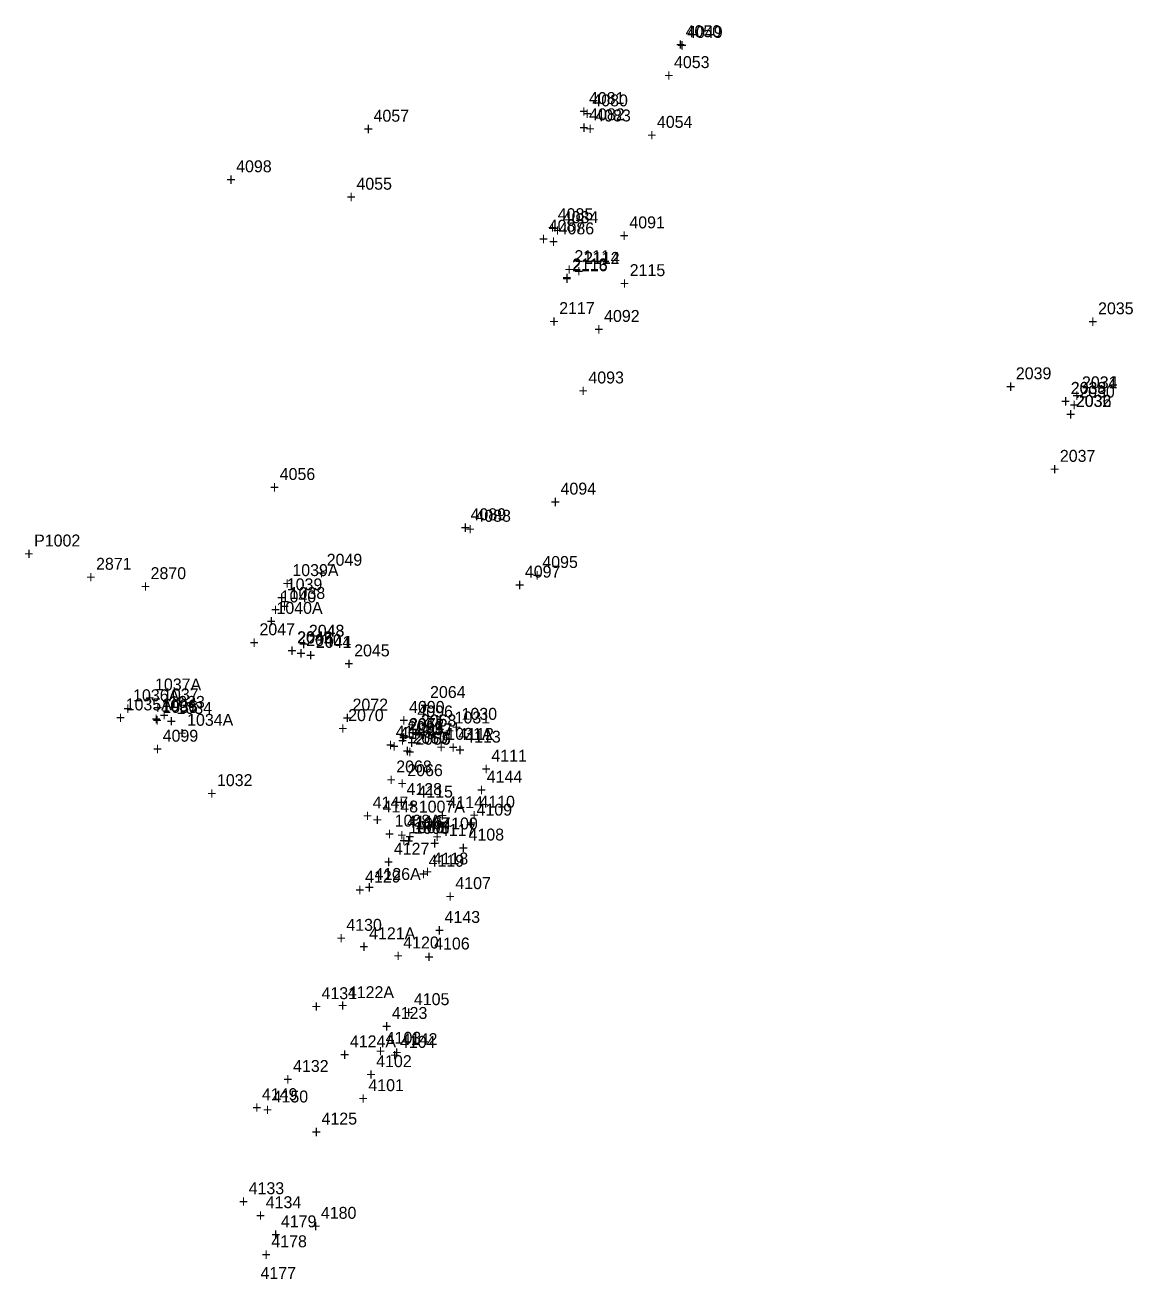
# Model space of a CAD drawing. Extents: x 1136220 to 1137808, y 528804 to 531215.
# Drawn here: x 1137240.3 to 1137472.3, y 529359.7 to 529622.1 of the extents above; entities that cross this region are included whole.
import ezdxf

# ---------------------------------------------------------------- set-up
doc = ezdxf.new("R2010")
doc.units = 0
for name, color, linetype in [('S_Buildings_SillElevation', 7, 'Continuous'), ('S_Drainage_CB', 7, 'Continuous'), ('S_Drainage_Culvert_Top', 7, 'Continuous'), ('S_Drainage_Invert', 7, 'Continuous'), ('S_Drainage_MH', 7, 'Continuous'), ('S_Drainage_Sump', 7, 'Continuous'), ('S_Fencing_PostAndRail', 7, 'Continuous'), ('S_Ground_Elevation', 7, 'Continuous'), ('S_Ground_LevelString', 7, 'Continuous'), ('S_Ground_SpotElevation', 7, 'Continuous'), ('S_Property_IronPipeFound', 7, 'Continuous'), ('S_Property_RockBoulder', 7, 'Continuous'), ('S_Roadway_Edge_Pavement', 7, 'Continuous'), ('S_Utilities_Gas_Gate', 7, 'Continuous'), ('S_Utilities_UG_Gas_Line', 7, 'Continuous'), ('S_Utilities_UG_Sanitary_MH', 7, 'Continuous'), ('S_Utilities_UG_Water_Gate', 7, 'Continuous'), ('S_Utilities_UG_Water_Line', 7, 'Continuous'), ('S_Utilities_UG_Water_Shutoff', 7, 'Continuous')]:
    doc.layers.add(name, color=color, linetype=linetype)

msp = doc.modelspace()

# ---------------------------------------------------------------- texts
at = {"layer": 'S_Buildings_SillElevation'}
for s, p in [('4053', (1137376.19, 529613.14)), ('+', (1137374.13, 529610.39)), ('4057', (1137313.27, 529601.92)), ('4054', (1137372.61, 529600.63)), ('+', (1137311.21, 529599.17)), ('+', (1137370.55, 529597.88)), ('4098', (1137284.5, 529591.33)), ('+', (1137282.44, 529588.58)), ('4055', (1137309.69, 529587.68)), ('+', (1137307.62, 529584.93)), ('4056', (1137293.62, 529526.91)), ('+', (1137291.56, 529524.16)), ('4099', (1137269.11, 529472.12)), ('+', (1137267.05, 529469.37)), ('4144', (1137336.97, 529463.55)), ('+', (1137334.91, 529460.8)), ('4143', (1137328.14, 529434.18)), ('+', (1137326.08, 529431.43)), ('4142', (1137319.21, 529408.6)), ('+', (1137317.15, 529405.85))]:
    msp.add_text(s, height=2.5, dxfattribs=at).set_placement(p)
at = {"layer": 'S_Drainage_CB'}
for s, p in [('1005', (1137321.71, 529452.85)), ('+', (1137319.65, 529450.1))]:
    msp.add_text(s, height=2.5, dxfattribs=at).set_placement(p)
at = {"layer": 'S_Drainage_Culvert_Top'}
for s, p in [('2116', (1137354.85, 529570.61)), ('2114', (1137357.37, 529572.17)), ('+', (1137355.3, 529569.42)), ('2115', (1137366.91, 529569.59)), ('+', (1137352.79, 529567.86)), ('+', (1137364.84, 529566.84)), ('2117', (1137352.14, 529561.64)), ('2035', (1137464.99, 529561.6)), ('+', (1137350.08, 529558.89)), ('+', (1137462.93, 529558.85)), ('2039', (1137447.77, 529547.99)), ('+', (1137445.71, 529545.24)), ('2038', (1137459.28, 529544.94)), ('2034', (1137461.63, 529546.1)), ('+', (1137457.22, 529542.19)), ('+', (1137459.57, 529543.35)), ('2036', (1137460.37, 529542.21)), ('+', (1137458.3, 529539.46)), ('2037', (1137456.99, 529530.71)), ('+', (1137454.93, 529527.96)), ('2049', (1137303.46, 529508.96)), ('1039A', (1137296.27, 529506.79)), ('+', (1137301.4, 529506.21)), ('+', (1137294.21, 529504.04)), ('1040A', (1137292.94, 529498.88)), ('2047', (1137289.38, 529494.41)), ('+', (1137290.88, 529496.13)), ('2048', (1137299.74, 529494.09)), ('2046', (1137297.32, 529492.69)), ('2044', (1137301.17, 529491.78)), ('+', (1137287.31, 529491.66)), ('+', (1137295.26, 529489.94)), ('+', (1137297.68, 529491.34)), ('2045', (1137309.21, 529489.98)), ('+', (1137299.11, 529489.03)), ('+', (1137307.14, 529487.23)), ('1037A', (1137267.51, 529482.85)), ('2064', (1137325.1, 529481.27)), ('1035A', (1137261.36, 529478.67)), ('1036A', (1137262.91, 529480.59)), ('+', (1137265.45, 529480.1)), ('2072', (1137308.87, 529478.64)), ('+', (1137260.85, 529477.84)), ('2070', (1137307.95, 529476.43)), ('+', (1137323.04, 529478.52)), ('+', (1137259.3, 529475.92)), ('1034A', (1137274.23, 529475.45)), ('+', (1137305.88, 529473.68)), ('+', (1137306.81, 529475.89)), ('2069', (1137320.41, 529473.9)), ('2071', (1137320.7, 529474.58)), ('2063', (1137323.17, 529475.32)), ('+', (1137272.17, 529472.7)), ('+', (1137318.35, 529471.15)), ('+', (1137318.64, 529471.83)), ('+', (1137321.1, 529472.57)), ('2067', (1137321.42, 529471.7)), ('2065', (1137321.97, 529471.49)), ('1031A', (1137328.52, 529472.51)), ('+', (1137319.36, 529468.95)), ('+', (1137319.91, 529468.74)), ('+', (1137326.46, 529469.76)), ('2068', (1137318.03, 529465.68)), ('2066', (1137320.34, 529464.91)), ('+', (1137315.97, 529462.93)), ('+', (1137318.28, 529462.16)), ('1007A', (1137322.74, 529457.28)), ('1008A', (1137317.7, 529454.34)), ('+', (1137320.68, 529454.53)), ('+', (1137315.64, 529451.59))]:
    msp.add_text(s, height=2.5, dxfattribs=at).set_placement(p)
at = {"layer": 'S_Drainage_Invert'}
for s, p in [('2113', (1137354.86, 529570.79)), ('2112', (1137357.35, 529572.15)), ('+', (1137352.79, 529568.04)), ('+', (1137355.28, 529569.4)), ('2033', (1137459.25, 529544.91)), ('2031', (1137461.61, 529546.11)), ('+', (1137457.19, 529542.16)), ('+', (1137459.55, 529543.36)), ('2032', (1137460.31, 529542.21)), ('+', (1137458.25, 529539.46)), ('1039', (1137295.1, 529503.81)), ('+', (1137293.04, 529501.06)), ('1040', (1137293.82, 529501.28)), ('+', (1137291.76, 529498.53)), ('2043', (1137299.72, 529494.1)), ('2042', (1137297.25, 529492.74)), ('2041', (1137301.19, 529491.76)), ('+', (1137295.19, 529489.99)), ('+', (1137297.65, 529491.35)), ('+', (1137299.13, 529489.01)), ('1036', (1137268.84, 529478.43)), ('1037', (1137269.19, 529480.78)), ('+', (1137267.13, 529478.03)), ('1035', (1137269.03, 529478.15)), ('1034', (1137272.01, 529477.95)), ('1031', (1137330.24, 529475.93)), ('+', (1137266.78, 529475.68)), ('+', (1137266.97, 529475.4)), ('+', (1137269.95, 529475.2)), ('2061', (1137320.4, 529473.9)), ('2062', (1137320.61, 529474.48)), ('2058', (1137323.16, 529475.31)), ('+', (1137318.34, 529471.15)), ('+', (1137318.55, 529471.73)), ('+', (1137321.09, 529472.56)), ('2060', (1137321.42, 529471.7)), ('2059', (1137321.97, 529471.5)), ('+', (1137328.18, 529473.18)), ('+', (1137319.36, 529468.95)), ('+', (1137319.91, 529468.75)), ('1008', (1137320.7, 529452.96)), ('1007', (1137321.96, 529453.79)), ('+', (1137318.64, 529450.21)), ('+', (1137319.9, 529451.04))]:
    msp.add_text(s, height=2.5, dxfattribs=at).set_placement(p)
at = {"layer": 'S_Drainage_MH'}
for s, p in [('1032', (1137280.48, 529462.82)), ('+', (1137278.42, 529460.07))]:
    msp.add_text(s, height=2.5, dxfattribs=at).set_placement(p)
at = {"layer": 'S_Drainage_Sump'}
for s, p in [('1038', (1137295.7, 529502)), ('+', (1137293.64, 529499.25)), ('1033', (1137270.51, 529479.2)), ('+', (1137268.45, 529476.45)), ('1030', (1137331.7, 529476.7)), ('+', (1137329.64, 529473.95)), ('1006', (1137321.73, 529452.84)), ('+', (1137319.67, 529450.09))]:
    msp.add_text(s, height=2.5, dxfattribs=at).set_placement(p)
at = {"layer": 'S_Fencing_PostAndRail'}
for s, p in [('4049', (1137378.94, 529619.44)), ('+', (1137376.88, 529616.69))]:
    msp.add_text(s, height=2.5, dxfattribs=at).set_placement(p)
at = {"layer": 'S_Ground_Elevation'}
for s, p in [('4050', (1137378.61, 529619.61)), ('+', (1137376.55, 529616.86)), ('4091', (1137366.84, 529579.59)), ('+', (1137364.78, 529576.84)), ('4092', (1137361.55, 529560)), ('+', (1137359.49, 529557.25)), ('4093', (1137358.26, 529547.12)), ('+', (1137356.2, 529544.37)), ('4094', (1137352.43, 529523.85)), ('+', (1137350.37, 529521.1)), ('4095', (1137348.61, 529508.49)), ('+', (1137346.55, 529505.74))]:
    msp.add_text(s, height=2.5, dxfattribs=at).set_placement(p)
at = {"layer": 'S_Ground_LevelString'}
for s, p in [('4111', (1137337.94, 529467.94)), ('+', (1137335.88, 529465.19)), ('4110', (1137335.44, 529458.29)), ('+', (1137333.38, 529455.54)), ('4109', (1137334.84, 529456.64)), ('+', (1137332.78, 529453.89)), ('4108', (1137333.16, 529451.43)), ('+', (1137331.1, 529448.68)), ('4126A', (1137313.48, 529443.18)), ('+', (1137311.42, 529440.43)), ('4107', (1137330.4, 529441.26)), ('+', (1137328.34, 529438.51)), ('4121A', (1137312.34, 529430.76)), ('4106', (1137325.96, 529428.61)), ('+', (1137310.28, 529428.01)), ('+', (1137323.9, 529425.86)), ('4122A', (1137307.89, 529418.43)), ('4105', (1137321.72, 529416.97)), ('+', (1137305.82, 529415.68)), ('+', (1137319.66, 529414.22)), ('4124A', (1137308.31, 529408.13)), ('4103', (1137315.81, 529408.88)), ('4104', (1137318.79, 529408.03)), ('+', (1137306.25, 529405.38)), ('+', (1137313.75, 529406.13)), ('+', (1137316.73, 529405.28)), ('4102', (1137313.82, 529403.99)), ('+', (1137311.76, 529401.24)), ('4101', (1137312.19, 529398.96)), ('+', (1137310.13, 529396.21))]:
    msp.add_text(s, height=2.5, dxfattribs=at).set_placement(p)
at = {"layer": 'S_Ground_SpotElevation'}
for s, p in [('4128', (1137320.17, 529460.95)), ('+', (1137318.11, 529458.2)), ('4127', (1137317.52, 529448.46)), ('+', (1137315.45, 529445.71)), ('4119', (1137324.8, 529445.94)), ('4129', (1137311.5, 529442.63)), ('4126', (1137313.48, 529443.18)), ('+', (1137322.74, 529443.19)), ('+', (1137309.43, 529439.88)), ('+', (1137311.42, 529440.43)), ('4130', (1137307.57, 529432.53)), ('+', (1137305.51, 529429.78)), ('4121', (1137312.34, 529430.76)), ('4120', (1137319.49, 529428.83)), ('+', (1137310.28, 529428.01)), ('+', (1137317.43, 529426.08)), ('4131', (1137302.38, 529418.22)), ('4122', (1137307.89, 529418.43)), ('+', (1137300.32, 529415.47)), ('+', (1137305.82, 529415.68)), ('4123', (1137317.1, 529414.08)), ('+', (1137315.04, 529411.33)), ('4124', (1137308.31, 529408.13)), ('+', (1137306.25, 529405.38)), ('4132', (1137296.42, 529402.98)), ('+', (1137294.36, 529400.23)), ('4133', (1137287.12, 529377.39)), ('+', (1137285.06, 529374.64)), ('4134', (1137290.69, 529374.46)), ('+', (1137288.62, 529371.71))]:
    msp.add_text(s, height=2.5, dxfattribs=at).set_placement(p)
at = {"layer": 'S_Property_IronPipeFound'}
for s, p in [('P1002', (1137242.19, 529512.99)), ('+', (1137240.13, 529510.24))]:
    msp.add_text(s, height=2.5, dxfattribs=at).set_placement(p)
at = {"layer": 'S_Property_RockBoulder'}
for s, p in [('4180', (1137302.24, 529372.24)), ('4179', (1137293.87, 529370.45)), ('+', (1137300.18, 529369.49)), ('4178', (1137291.87, 529366.28)), ('+', (1137291.81, 529367.7)), ('+', (1137289.81, 529363.53)), ('4177', (1137289.6, 529359.65))]:
    msp.add_text(s, height=2.5, dxfattribs=at).set_placement(p)
at = {"layer": 'S_Roadway_Edge_Pavement'}
for s, p in [('4112', (1137331.04, 529472.46)), ('4113', (1137332.47, 529471.92)), ('+', (1137328.97, 529469.71)), ('+', (1137330.4, 529469.17)), ('4115', (1137322.45, 529460.42)), ('4114', (1137328.76, 529458.21)), ('+', (1137320.39, 529457.67)), ('+', (1137326.7, 529455.46)), ('4116', (1137320.26, 529454.1)), ('4117', (1137327.16, 529452.38)), ('+', (1137318.2, 529451.35)), ('+', (1137325.1, 529449.63)), ('4118', (1137325.66, 529446.42)), ('+', (1137323.6, 529443.67))]:
    msp.add_text(s, height=2.5, dxfattribs=at).set_placement(p)
at = {"layer": 'S_Utilities_Gas_Gate'}
for s, p in [('2870', (1137266.58, 529506.15)), ('+', (1137264.52, 529503.4))]:
    msp.add_text(s, height=2.5, dxfattribs=at).set_placement(p)
at = {"layer": 'S_Utilities_UG_Gas_Line'}
for s, p in [('2871', (1137255.16, 529508.11)), ('+', (1137253.1, 529505.36))]:
    msp.add_text(s, height=2.5, dxfattribs=at).set_placement(p)
at = {"layer": 'S_Utilities_UG_Sanitary_MH'}
for s, p in [('2111', (1137355.33, 529572.52)), ('+', (1137353.27, 529569.77)), ('2030', (1137461.05, 529544.16)), ('+', (1137458.99, 529541.41)), ('2040', (1137299.17, 529492.15)), ('+', (1137297.11, 529489.4)), ('2057', (1137322.35, 529473.47)), ('+', (1137320.29, 529470.72))]:
    msp.add_text(s, height=2.5, dxfattribs=at).set_placement(p)
at = {"layer": 'S_Utilities_UG_Water_Gate'}
for s, p in [('4086', (1137352.03, 529578.33)), ('+', (1137349.97, 529575.58)), ('4125', (1137302.38, 529391.96)), ('+', (1137300.32, 529389.21))]:
    msp.add_text(s, height=2.5, dxfattribs=at).set_placement(p)
at = {"layer": 'S_Utilities_UG_Water_Line'}
for s, p in [('4081', (1137358.38, 529605.61)), ('4080', (1137359.09, 529605.13)), ('+', (1137356.32, 529602.86)), ('+', (1137357.02, 529602.38)), ('4082', (1137358.41, 529602.21)), ('4083', (1137359.7, 529601.97)), ('+', (1137356.35, 529599.46)), ('+', (1137357.64, 529599.22)), ('4085', (1137351.83, 529581.3)), ('4084', (1137352.89, 529580.68)), ('+', (1137349.77, 529578.55)), ('4087', (1137349.95, 529578.9)), ('+', (1137347.89, 529576.15)), ('+', (1137350.83, 529577.93)), ('4089', (1137333.58, 529518.48)), ('4088', (1137334.6, 529518.16)), ('+', (1137331.52, 529515.73)), ('+', (1137332.54, 529515.41)), ('4090', (1137320.71, 529478.15)), ('4096', (1137322.46, 529477.2)), ('+', (1137318.64, 529475.4)), ('+', (1137320.4, 529474.45)), ('4146', (1137317.91, 529472.97)), ('4145', (1137318.68, 529472.68)), ('+', (1137315.84, 529470.22)), ('+', (1137316.62, 529469.93)), ('4147', (1137313.1, 529458.14)), ('+', (1137311.04, 529455.39)), ('4148', (1137315.15, 529457.3)), ('+', (1137313.09, 529454.55)), ('4149', (1137289.9, 529397.07)), ('4150', (1137292.13, 529396.59)), ('+', (1137287.84, 529394.32)), ('+', (1137290.07, 529393.84))]:
    msp.add_text(s, height=2.5, dxfattribs=at).set_placement(p)
at = {"layer": 'S_Utilities_UG_Water_Shutoff'}
for s, p in [('4097', (1137344.96, 529506.48)), ('+', (1137342.9, 529503.73)), ('4100', (1137327.66, 529453.75)), ('+', (1137325.6, 529451))]:
    msp.add_text(s, height=2.5, dxfattribs=at).set_placement(p)

doc.saveas('drawing.dxf')
